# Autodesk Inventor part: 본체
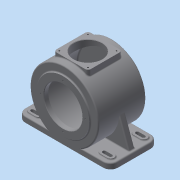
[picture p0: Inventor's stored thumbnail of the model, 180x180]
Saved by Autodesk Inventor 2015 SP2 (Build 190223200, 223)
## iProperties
Created: 2015-06
Part Number: 본체
Material: 일반
Document SubType Name: Modeling
Designer: AMC
Density: 1 g/cm^3
Appearance: 기본값
Author: AMC
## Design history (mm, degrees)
sketch "스케치1"
  geometry: L1 (-115, 59)-(115, 59); L2 (115, 59)-(115, -59); L3 (115, -59)-(-115, -59); L4 (-115, -59)-(-115, 59); 3 further points
  constraints: 8 end point, 2 midpoint, 2 parallel, 1 horizontal, 1 horizontal alignment, 1 perpendicular, 1 vertical alignment
  dimensions: "d0" = 230 distance of L2.end L3.end; "d1" = 118 distance of L1.end L2.end
extrude "돌출1" new body sketch "스케치1" distance "d2" = 14; taper "d3" = 0 deg
sketch "스케치2"
  geometry: L1 (81, 41)-(97, 41); L2 (81, 50)-(97, 50); L3 (97, 32)-(81, 32); L4 (115, 59)-(-115, 59) reference; A1 r 9 centre (81, 41) between (81, 50) and (81, 32); A2 r 9 centre (97, 41) between (97, 32) and (97, 50); 2 further points
  constraints: 8 end point, 4 point on circle, 4 tangent, 2 centre point, 1 horizontal, 1 midpoint, 1 parallel
  dimensions: "d4" = 16 distance of L1.end L1.start; "d5" = 18 distance between parallel lines of L3 L2; "d6" = 97 horizontal distance of point (0, 0) L1.end; "d7" = 18 distance from line of L4 point (89, 41)
extrude "돌출2" join sketch "스케치2" distance "d8" = 3; taper "d9" = 0 deg
sketch "스케치3"
  geometry: L1 (97, 32)-(81, 32) reference; L2 (81, 50)-(97, 50) reference; L3 (81, 41)-(97, 41); L4 (81, 45)-(97, 45); L5 (97, 37)-(81, 37); A1 r 9 centre (97, 41) between (97, 32) and (97, 50) reference; A2 r 9 centre (81, 41) between (81, 50) and (81, 32) reference; A3 r 9 centre (81, 41) between (81, 50) and (81, 32) reference; A4 r 4 centre (81, 41) between (81, 45) and (81, 37); A5 r 4 centre (97, 41) between (97, 37) and (97, 45); 2 further points
  constraints: 8 end point, 4 point on circle, 4 tangent, 2 centre point, 1 horizontal, 1 midpoint, 1 parallel
  dimensions: "d10" = 8 distance between parallel lines of L5 L4
extrude "돌출3" cut sketch "스케치3" stored distance "d11" = 3; taper "d12" = 0 deg
sketch "스케치4"
  geometry: L1 (115, 14)-(115, 0) reference; L2 (115, 0)-(-115, 0) reference; L3 (-115, 0)-(-115, 14) reference; L4 (-115, 14)-(115, 14) reference; L5 (-115, 0)-(115, 0) reference; C1 r 85 at (0, 85); 3 further points
  constraints: 2 midpoint, 1 centre point, 1 vertical alignment
  dimensions: "d15" = 170 diameter of C1; "d16" = 85 distance from line of C1.centre L2
extrude "돌출4" join sketch "스케치4" stored distance "d17" = 118; taper "d18" = 0 deg
sketch "스케치5"
  geometry: L1 (115, 0)-(-115, 0) reference; L2 (-115, 0)-(-115, 14) reference; L3 (-115, 14)-(-46.733, 14) reference; L4 (46.733, 14)-(115, 14) reference; L5 (115, 14)-(115, 0) reference; L6 (46.733, 14)-(115, 14) reference; L7 (109, 14)-(84.87, 80.297); A1 r 85 centre (0, 85) between (46.733, 14) and (-46.733, 14) reference; 1 further point
  constraints: 2 end point, 1 point on circle, 1 point on line
  dimensions: "d19" = 6 distance from line of L7.start L5; "d20" = 110 deg angle of L4 L7
feature "리브1" sketch "스케치5" dims "d21" = 1, "d22" = 15, "d23" = 0, "d24" = 0, "d25" = 1, "d26" = 1
sketch "스케치6"
  geometry: L1 (161.733, 14)-(230, 14) reference; L2 (230, 14)-(230, 0) reference; L3 (230, 0)-(0, 0) reference; L4 (0, 0)-(0, 14) reference; L5 (0, 14)-(68.267, 14) reference; C1 r 65 at (115, 85); A1 r 85 centre (115, 85) between (161.733, 14) and (68.267, 14) reference; 1 further point
  constraints: 1 centre point, 1 coincident
  dimensions: "d27" = 130 diameter of C1
extrude "돌출5" join sketch "스케치6" distance "d28" = 3; taper "d29" = 0 deg
sketch "스케치7"
  geometry: C1 r 47.5 at (0, 0); C2 r 65 at (0, 0) reference; 1 further point
  constraints: 1 centre point, 1 coincident
  dimensions: "d30" = 95 diameter of C1
extrude "돌출6" cut sketch "스케치7" distance "d31" = 11; taper "d32" = 0 deg
node "작업 평면2"
  node "작업 평면1"
sketch "스케치8"
  geometry: L1 (-42.5, 42.5)-(42.5, 42.5); L2 (42.5, 42.5)-(42.5, -42.5); L3 (42.5, -42.5)-(-42.5, -42.5); L4 (-42.5, -42.5)-(-42.5, 42.5); 3 further points
  constraints: 8 end point, 2 midpoint, 2 parallel, 1 horizontal, 1 horizontal alignment, 1 perpendicular, 1 vertical alignment
  dimensions: "d34" = 85 distance of L1.start L1.end; "d35" = 85 distance of L1.end L2.end
extrude "돌출7" join sketch "스케치8" stored distance "d36" = 11; taper "d37" = 0 deg
sketch "스케치9"
  geometry: L1 (-51, 162)-(51, 162); L2 (51, 162)-(51, 8); L3 (51, 8)-(-51, 8); L4 (-51, 8)-(-51, 162); L5 (-59, 0)-(59, 0) reference; L6 (-59, 170)-(-59, 14) reference; L7 (59, 14)-(59, 170) reference; L8 (51, 85)-(-51, 85); 1 further point
  constraints: 10 end point, 2 midpoint, 2 parallel, 1 horizontal, 1 perpendicular
  dimensions: "d38" = 8 distance between parallel lines of L5 L3; "d39" = 8 distance between parallel lines of L6 L4; "d40" = 8 distance between parallel lines of L7 L2; "d41" = 154 distance of L1.end L2.end
revolve "회전1" sketch "스케치9" stored, may be unused: angle "d42" = 90 deg
sketch "스케치10"
  geometry: C1 r 35 at (0, 0); 1 further point
  constraints: 1 centre point, 1 coincident
  dimensions: "d43" = 70 diameter of C1
extrude "돌출8" cut sketch "스케치10" distance "d44" = 48; taper "d45" = 0 deg
sketch "스케치11"
  geometry: 2 further points
  dimensions: "d46" = 35.5 horizontal distance of point (0, 0) point (35.5, 35.5); "d47" = 35.5 horizontal distance of point (0, 0) point (35.5, 35.5)
hole "구멍1" sketch "스케치11" at (35.5, 35.5) diameter "d48" = 3.242; stored, may be unused: countersink angle "d52" = 90 deg, drill point angle "d54" = 118 deg; dims "d49" = 10, "d50" = 4, "d51" = 2, "d53" = 13
fillet "모깎기1" dims "d58" = 7
fillet "모깎기2" dims "d59" = 18
fillet "모깎기3" dims "d60" = 3
sketch "스케치12"
  geometry: L1 (55.179, -11)-(0, -11) reference; L2 (0, 0)-(0, -11) reference; L3 (0, 0)-(194, 0) reference; L4 (194, 0)-(194, -11) reference; L5 (194, -11)-(138.821, -11) reference; C1 r 65 at (97, -85); A1 r 85 centre (97, -85) between (55.179, -11) and (138.821, -11) reference; 1 further point
  constraints: 1 centre point, 1 coincident
  dimensions: "d61" = 130 diameter of C1
extrude "돌출9" join sketch "스케치12" distance "d62" = 13; taper "d63" = 0 deg
sketch "스케치21"
  geometry: L1 (-108.18, -71)-(-46.733, -71) reference; L2 (46.733, -71)-(108.18, -71) reference; L3 (111.967, -74)-(111.967, -85) reference; L4 (111.967, -85)-(-111.967, -85) reference; L5 (-111.967, -85)-(-111.967, -74) reference; C1 r 77 at (0, 0) reference; C2 r 31 at (0, 0); A1 r 85 centre (0, 0) between (46.733, -71) and (-46.733, -71) reference; 1 further point
  constraints: 1 centre point, 1 coincident, 2 other
  dimensions: "d73" = 62 diameter of C2
extrude "돌출13" join sketch "스케치21" distance "d74" = 3.5; taper "d75" = -25 deg
sketch "스케치23"
  geometry: L1 (46.733, -71)-(74.775, -71) reference; L2 (74.775, -71)-(74.775, -68) reference; L3 (74.775, -68)-(103.225, -68) reference; L4 (103.225, -68)-(103.225, -71) reference; L5 (103.225, -71)-(110.519, -71) reference; L6 (113.785, -74)-(113.785, -85) reference; L7 (113.785, -85)-(-113.785, -85) reference; L8 (-113.785, -85)-(-113.785, -74) reference; L9 (-110.519, -71)-(-103.225, -71) reference; L10 (-103.225, -71)-(-103.225, -68) reference; L11 (-103.225, -68)-(-74.775, -68) reference; L12 (-74.775, -68)-(-74.775, -71) reference; L13 (-74.775, -71)-(-46.733, -71) reference; C1 r 29.368 at (0, 0) reference; C2 r 77 at (0, 0) reference; C3 r 23.5 at (0, 0); A1 r 85 centre (0, 0) between (46.733, -71) and (-46.733, -71) reference; 1 further point
  constraints: 1 centre point, 1 coincident, 2 other
  dimensions: "d76" = 47 diameter of C3
extrude "돌출14" cut sketch "스케치23" distance "d77" = 14; taper "d78" = 0 deg
sketch "스케치24"
  geometry: C1 r 23.5 at (0, 0) reference; C2 r 65 at (0, 0) reference; C3 r 15 at (0, 0); 1 further point
  constraints: 1 centre point, 1 coincident
  dimensions: "d79" = 30 diameter of C3
extrude "돌출15" cut sketch "스케치24" distance "d80" = 3; taper "d81" = 0 deg
sketch "스케치26"
  geometry: C1 r 47.5 at (0, 0) reference; C2 r 65 at (0, 0) reference; 2 further points
  constraints: 1 vertical alignment
  dimensions: "d82" = 55 distance of C1.centre point (0, 55)
hole "구멍2" sketch "스케치26" at (0, 55) diameter "d83" = 3.242; stored, may be unused: countersink angle "d87" = 90 deg, drill point angle "d89" = 118 deg; dims "d84" = 8, "d85" = 4, "d86" = 2, "d88" = 11.8
sketch "스케치27"
  geometry: 1 further point
chamfer "모따기1" distance "d93" = 1; stored, may be unused: second distance "d94" = 2, angle "d95" = 45 deg
fillet "모깎기4" dims "d96" = 3
fillet "모깎기5" dims "d97" = 3
fillet "모깎기6" dims "d98" = 3
fillet "모깎기7" dims "d99" = 3
fillet "모깎기8" dims "d100" = 3
fillet "모깎기9" dims "d101" = 3
fillet "모깎기10" dims "d102" = 3
chamfer "모따기2" distance "d103" = 1; stored, may be unused: second distance "d104" = 2, angle "d105" = 45 deg
fillet "모깎기11" dims "d106" = 3
fillet "모깎기12" dims "d107" = 3
fillet "모깎기13" dims "d108" = 3
node "솔리드1"
mirror "대칭1"
mirror "대칭2"
mirror "대칭3"
pattern_circular "원형 패턴1" dims angle "d56" = 360 deg
pattern_circular "원형 패턴2" dims angle "d91" = 360 deg
node "절단 모서리 투영1"
node "절단 모서리 투영2"
node "절단 모서리 투영3"
node "절단 모서리 투영4"
node "절단 모서리 투영5"
node "절단 모서리 투영6"
node "절단 모서리 투영11"
node "절단 모서리 투영13"
node "절단 모서리 투영14"
node "절단 모서리 투영15"
other parameters: "d33" = 3
